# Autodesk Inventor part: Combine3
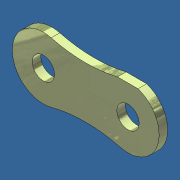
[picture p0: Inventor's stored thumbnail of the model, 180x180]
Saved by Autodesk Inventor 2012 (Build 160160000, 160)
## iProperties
Created: 2016-02
Part Number: Combine3
Material: Steel
Document SubType Name: Modeling
Designer: Admin
Density: 7.85 g/cm^3
Mass: 0.16658 g
Surface Area: 0.914635 cm^2
Volume: 0.0212203 cm^3
Translation Standard: STEP AP214IS
FileName: C:\AAATEMP\21.1713_1 Connecting Link Side Plate.stp
PreProcessor: Autodesk Inventor 2012
PostProcessor: Build: 160, Release: 2012 RTM - Date: Tue 03/01/2011
Sent Units: inch
Uncertainty: 0.00039370078740199997
Author: Admin
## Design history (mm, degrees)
feature "Base1"
sketch "Sketch1"
  geometry: L1 (2.255, -9.387)-(3.709, -9.387); A1 r 9.654 centre (0, 0) between (-2.441, -9.341) and (2.441, -9.341) reference; A2 r 2.202 centre (2.997, -11.471) between (2.441, -13.601) and (2.441, -9.341) reference; 1 further point
  constraints: 2 end point, 2 point on circle, 1 horizontal
extrude "FICTICIOUS FOR ALIGNMENT" cut sketch "Sketch1" distance "d0" = 25.4; taper "d1" = 0 deg
body "Solid1"
